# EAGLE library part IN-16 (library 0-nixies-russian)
IN-16: small numeric frontview nixie tube
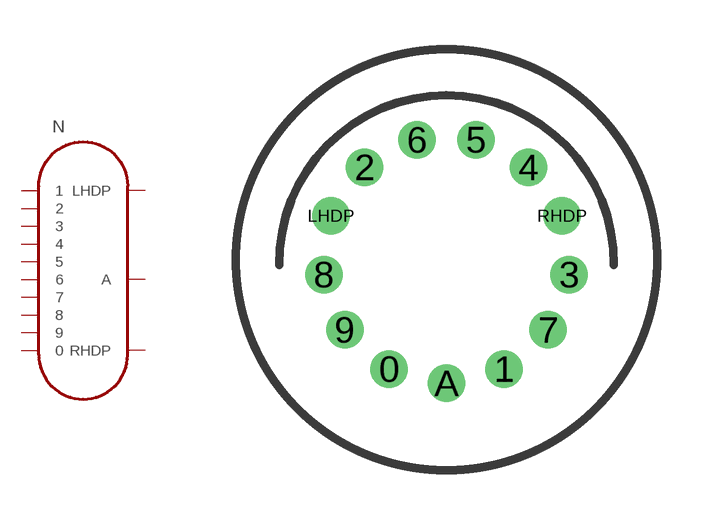
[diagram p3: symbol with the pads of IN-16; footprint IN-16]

Designator prefix N

## IN-16  [IN-16]
0  0
1  1
2  2
3  3
4  4
5  5
6  6
7  7
8  8
9  9
A  A
LHDP  LHDP
RHDP  RHDP

## Footprint IN-16 (pad centres in mm)
drill 0.63 round: 0 -1.745,-3.325; 1 1.745,-3.325; 2 -2.49,2.81; 3 3.727,-0.453; 4 2.49,2.81; 5 0.898,3.645; 6 -0.898,3.645; 7 3.09,-2.133; 8 -3.727,-0.453; 9 -3.09,-2.133; A 0,-3.755; LHDP -3.511,1.331; RHDP 3.511,1.331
